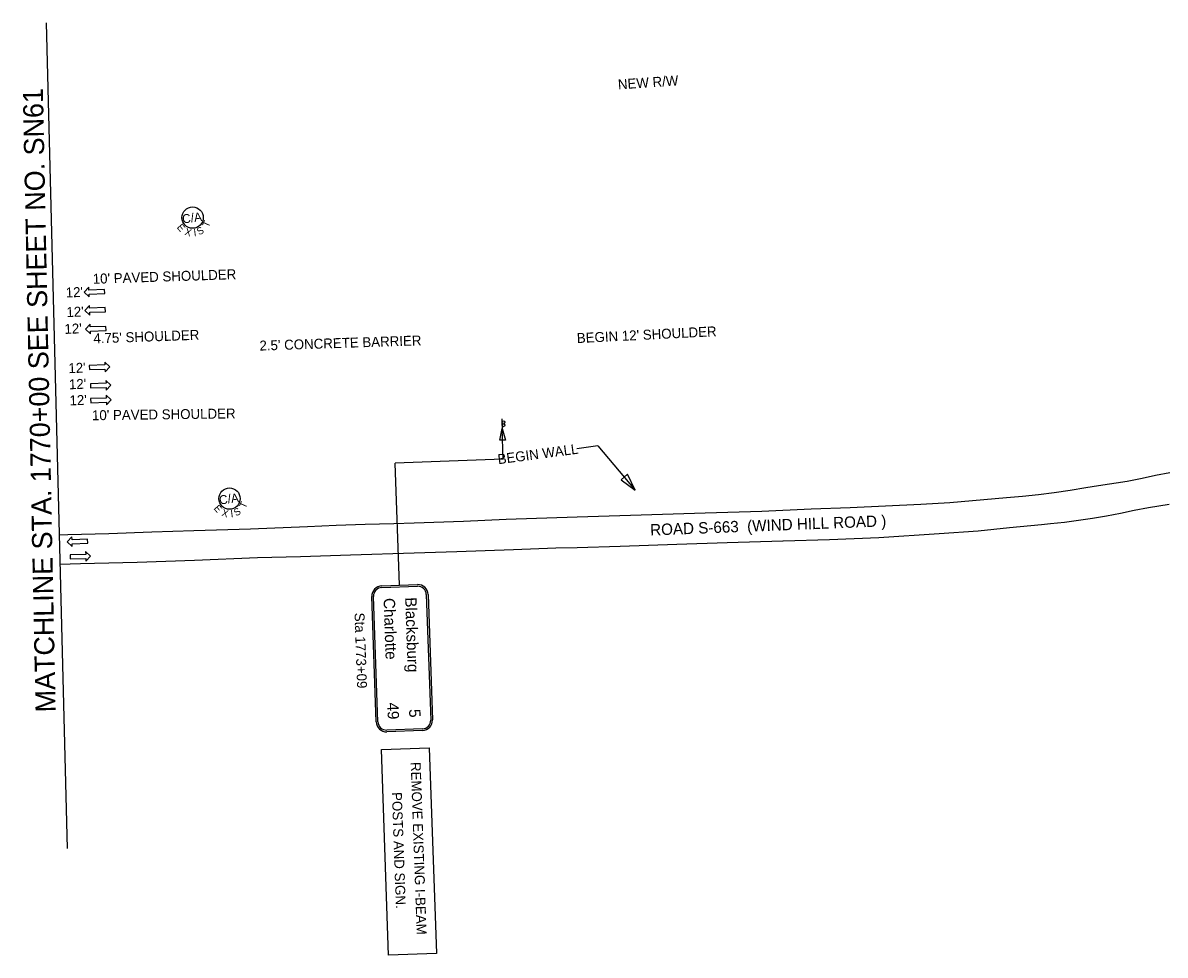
# Model space of a CAD drawing. Extents: x 1823450 to 1825059, y 1192489 to 1193580.
# Drawn here: x 1823450 to 1824254, y 1192489 to 1193146 of the extents above; entities that cross this region are included whole.
import ezdxf

# ---------------------------------------------------------------- set-up
doc = ezdxf.new("R2010")
doc.units = 0
for name, color, linetype in [('RD_EX_Road', 7, 'Continuous'), ('RD_PD_Final_LnLine', 7, 'Continuous'), ('RD_PD_Final_TX', 7, 'Continuous'), ('RD_PD_RW_TX', 7, 'Continuous'), ('RD_SHT_MatchLine', 7, 'Continuous'), ('RD_SHT_TX', 7, 'Continuous'), ('RD_Sketch8', 7, 'Continuous'), ('RD_TX_RoadID', 7, 'Continuous'), ('SN_P_Signs', 7, 'Continuous'), ('TERMINATOR', 7, 'Continuous')]:
    doc.layers.add(name, color=color, linetype=linetype)

# ---------------------------------------------------------------- blocks, each defined once
blk = doc.blocks.new('SARRW2')
at = {"layer": 'RD_PD_Final_LnLine'}
blk.add_lwpolyline([(-12, 1.2), (-12, -1.2), (-2.83, -1.2), (-2.83, -2.83), (0, 0), (-2.83, 2.83), (-2.83, 1.2)], close=True, dxfattribs=at)

msp = doc.modelspace()

# ---------------------------------------------------------------- linework, layer by layer
at = {"layer": 'RD_EX_Road'}
for points in [[(1824257.75, 1192828.74), (1824247.58, 1192826.84), (1824238.18, 1192824.59), (1824227.48, 1192822.54), (1824207.45, 1192819.53), (1824198.45, 1192817.95), (1824187.34, 1192816.18), (1824176.2, 1192814.61), (1824165.04, 1192813.23), (1824153.86, 1192812.05), (1824142.65, 1192811.07), (1824102.56, 1192807.44), (1824082.25, 1192806.31), (1824032.56, 1192804.04), (1824005.06, 1192803.02), (1823970.23, 1192801.37), (1823930.27, 1192800.33), (1823885.22, 1192798.88), (1823840.13, 1192797.43), (1823790.06, 1192795.71), (1823760.14, 1192794.43), (1823725.28, 1192793.07), (1823711.02, 1192792.81), (1823690.74, 1192792.29), (1823670.46, 1192791.57), (1823650.18, 1192790.65), (1823610.15, 1192789.06), (1823570.12, 1192787.69), (1823540.6, 1192786.79), (1823510.26, 1192785.73), (1823481.25, 1192785.01), (1823475.22, 1192784.82)], [(1823985.24, 1192780.63), (1824018.01, 1192781.77), (1824052.57, 1192783.14), (1824095.27, 1192785.83), (1824122.62, 1192787.75), (1824144.63, 1192790.09), (1824167.3, 1192792.31), (1824173.5, 1192792.89), (1824183.41, 1192793.96), (1824193.3, 1192795.23), (1824203.16, 1192796.7), (1824212.99, 1192798.36), (1824222.79, 1192800.22), (1824232.54, 1192802.27), (1824242.73, 1192804.3), (1824257.25, 1192806.65)], [(1823985.11, 1192780.6), (1823945.8, 1192779.26), (1823910.27, 1192778.11), (1823870.34, 1192776.75), (1823840.12, 1192775.91), (1823825.2, 1192775.48), (1823795.37, 1192774.38), (1823755.33, 1192773.02), (1823725.28, 1192772.15), (1823680.39, 1192770.7), (1823645.36, 1192769.42), (1823615.05, 1192768.77), (1823570.55, 1192766.91), (1823530.13, 1192765.57), (1823500.17, 1192764.75), (1823490.23, 1192764.49), (1823475.75, 1192764.01)]]:
    msp.add_lwpolyline(points, dxfattribs=at)
at = {"layer": 'RD_PD_Final_TX'}
for q in [(1823839.94, 1192845.64), (1823881.09, 1192816.52)]:
    msp.add_line((1823854.69, 1192847.6), q, dxfattribs=at)
at = {"layer": 'RD_SHT_MatchLine'}
msp.add_line((1823465.99, 1193145.54), (1823480.87, 1192564.03), dxfattribs=at)
at = {"layer": 'RD_Sketch8'}
for centre in [(1823569.25, 1193008.4), (1823595.26, 1192810.49)]:
    msp.add_circle(centre, 7.5, dxfattribs=at)
at = {"layer": 'SN_P_Signs'}
for p, q in [((1823787.14, 1192866.58), (1823787.27, 1192862.08)), ((1823787.19, 1192864.34), (1823787.32, 1192859.84)), ((1823788.13, 1192838.16), (1823787.37, 1192859.85)), ((1823788.13, 1192838.16), (1823712.03, 1192835.49)), ((1823715.05, 1192749.5), (1823712.03, 1192835.49)), ((1823733.89, 1192742.95), (1823736.99, 1192654.54)), ((1823735.09, 1192742.99), (1823738.19, 1192654.58)), ((1823702.28, 1192633.88), (1823735.88, 1192635.06)), ((1823707.36, 1192488.95), (1823702.28, 1192633.88)), ((1823735.88, 1192635.06), (1823740.96, 1192490.13)), ((1823740.96, 1192490.13), (1823707.36, 1192488.95))]:
    msp.add_line(p, q, dxfattribs=at)
msp.add_lwpolyline([(1823785.61, 1192851.58), (1823787.37, 1192859.85), (1823789.71, 1192851.72)], close=True, dxfattribs=at)
for points in [[(1823702.46, 1192749.06), (1823727.64, 1192749.94)], [(1823698.61, 1192653.19), (1823695.51, 1192741.61)], [(1823699.81, 1192653.23), (1823696.71, 1192741.65)], [(1823702.5, 1192747.86), (1823727.68, 1192748.74)], [(1823731.2, 1192648.33), (1823706.02, 1192647.45)], [(1823731.24, 1192647.13), (1823706.06, 1192646.25)]]:
    msp.add_lwpolyline(points, dxfattribs=at)
for centre in [(1823788.22, 1192864.35), (1823788.27, 1192862.11)]:
    msp.add_circle(centre, 1, dxfattribs=at)
for centre, radius, start, end in [((1823727.89, 1192742.74), 7.2, 2.00774, 92.00774), ((1823702.71, 1192741.86), 7.2, 92.00774, 182.00774), ((1823702.71, 1192741.86), 6, 92.00774, 182.00774), ((1823727.89, 1192742.74), 6, 2.00774, 92.00774), ((1823705.81, 1192653.44), 7.2, 182.00774, 272.00774), ((1823705.81, 1192653.44), 6, 182.00774, 272.00774), ((1823730.99, 1192654.33), 6, 272.00774, 2.00774), ((1823730.99, 1192654.33), 7.2, 272.00774, 2.00774)]:
    msp.add_arc(centre, radius, start, end, dxfattribs=at)
at = {"layer": 'TERMINATOR'}
msp.add_lwpolyline([(1823871.04, 1192823.72), (1823881.09, 1192816.52), (1823875.61, 1192827.6)], close=True, dxfattribs=at)

# ---------------------------------------------------------------- block references
at = {"layer": 'RD_PD_Final_LnLine'}
for p, xscale, yscale, rotation in [((1823492.91, 1192955.82), 1.2000000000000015, 1.2000000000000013, -177.99225385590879), ((1823493.35, 1192943.05), 1.2000000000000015, 1.2000000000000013, -177.99225385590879), ((1823493.82, 1192929.81), 1.2000000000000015, 1.2000000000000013, -177.99225385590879), ((1823510.86, 1192903.26), 1.200000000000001, 1.2000000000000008, 2.007829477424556), ((1823511.74, 1192890.38), 1.200000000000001, 1.2000000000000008, 2.007829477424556), ((1823511.85, 1192879.95), 1.200000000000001, 1.2000000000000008, 2.007829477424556), ((1823480.98, 1192779.96), 1.2000000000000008, 1.200000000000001, -177.99217052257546), ((1823497.4, 1192769.9), 1.200000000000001, 1.2000000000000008, 2.007829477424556)]:
    msp.add_blockref('SARRW2', p, dxfattribs=dict(at, xscale=xscale, yscale=yscale, rotation=rotation))

# ---------------------------------------------------------------- texts
at = {"layer": 'RD_PD_Final_TX'}
for s, rotation, p in [("10' PAVED SHOULDER", 1.88215, (1823499.01, 1192961.72)), ("12'", 2.21446, (1823480.01, 1192952.08)), ("12'", 2.21446, (1823480.49, 1192938.29)), ("12'", 2.21446, (1823479.12, 1192926.44)), ("4.75' SHOULDER", 2.00775, (1823499.52, 1192919.76)), ("BEGIN 12' SHOULDER", 2.85127, (1823840.09, 1192919.99)), ("2.5' CONCRETE BARRIER", 1.88215, (1823616.47, 1192914.7)), ("12'", 2.21446, (1823481.88, 1192898.78)), ("12'", 2.21446, (1823482.28, 1192887.44)), ("12'", 2.21446, (1823482.67, 1192876.11)), ("10' PAVED SHOULDER", 0.75072, (1823498.42, 1192865.66)), ('BEGIN WALL', 7.56198, (1823784.63, 1192834.65))]:
    msp.add_text(s, height=7, rotation=rotation, dxfattribs=at).set_placement(p)
at = {"layer": 'RD_PD_RW_TX'}
msp.add_text('NEW R/W', height=7, rotation=3.95937, dxfattribs=at).set_placement((1823869.11, 1193098.62))
at = {"layer": 'RD_SHT_TX'}
msp.add_text('MATCHLINE STA. 1770+00 SEE SHEET NO. SN61', height=14.1726, rotation=91.1747, dxfattribs=at).set_placement((1823472.81, 1192660.07))
at = {"layer": 'RD_Sketch8'}
for s, height, rotation, p in [('C/A', 6.25, 7.31198, (1823562.31, 1193004.21)), ('E', 5, 310.52322, (1823557.83, 1193001.37)), ('X', 5, 342.9526, (1823563.29, 1192996.37)), ('I', 5, 7.1126, (1823570.28, 1192995.18)), ('S', 5, 29.10442, (1823573.88, 1192995.82)), ('T', 5, 65.49713, (1823580.46, 1193001.06)), ('C/A', 6.25, 7.31198, (1823588.33, 1192806.29)), ('E', 5, 310.52322, (1823583.84, 1192803.46)), ('T', 5, 65.49713, (1823606.48, 1192803.15)), ('X', 5, 342.9526, (1823589.3, 1192798.46)), ('I', 5, 7.1126, (1823596.3, 1192797.27)), ('S', 5, 29.10442, (1823599.89, 1192797.9))]:
    msp.add_text(s, height=height, rotation=rotation, dxfattribs=at).set_placement(p)
at = {"layer": 'RD_TX_RoadID'}
msp.add_text('ROAD S-663  (WIND HILL ROAD )', height=8, rotation=2.23942, dxfattribs=at).set_placement((1823891.72, 1192784.45))
at = {"layer": 'SN_P_Signs'}
for s, height, rotation, p in [('Charlotte', 8, 272.00774, (1823703.76, 1192740.33)), ('Blacksburg', 8, 272.00774, (1823718.95, 1192740.86)), ('Sta 1773+09', 7, 272.00783, (1823683.29, 1192730.01)), ('49', 8, 272.00774, (1823706.34, 1192666.74)), ('5', 8, 272.00774, (1823721.71, 1192662.12)), ('REMOVE EXISTING I-BEAM', 6.9998, 272.00783, (1823722.87, 1192624.85)), ('POSTS AND SIGN. ', 6.9998, 272.00783, (1823709.6, 1192603.67))]:
    msp.add_text(s, height=height, rotation=rotation, dxfattribs=at).set_placement(p)

doc.saveas('drawing.dxf')
